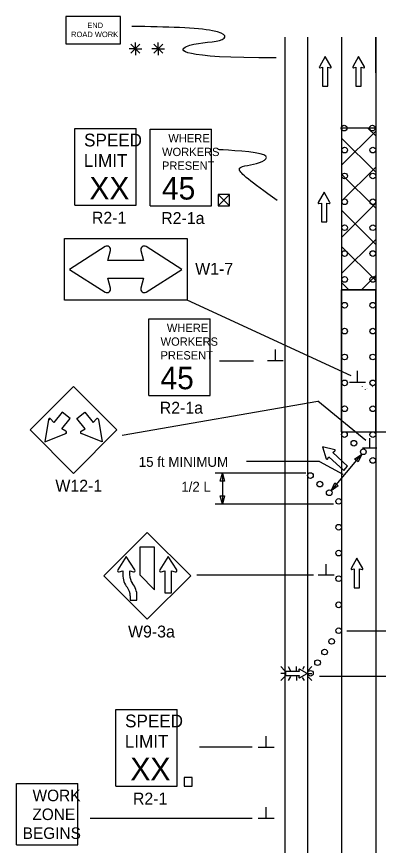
# Model space of a CAD drawing. Extents: x 16728 to 18482, y 5716 to 6919.
# Drawn here: x 16749 to 17004, y 6311 to 6894 of the extents above; entities that cross this region are included whole.
import ezdxf

# ---------------------------------------------------------------- set-up
doc = ezdxf.new("R2010")
doc.units = 0
for name, color, linetype in [('ALI_LEGAL_EX', 7, 'Continuous'), ('MT_SCRATCH_LEVEL_E', 7, 'Continuous'), ('PAVT_EDGE_EX', 7, 'Continuous'), ('TRAFFIC_SIGNS_PR', 7, 'Continuous'), ('TYPICAL_TEXT_DIMEN_PR', 7, 'Continuous')]:
    doc.layers.add(name, color=color, linetype=linetype)

msp = doc.modelspace()

# ---------------------------------------------------------------- linework, layer by layer
at = {"layer": 'ALI_LEGAL_EX'}
for p, q in [((16978.2, 6879.62), (16978.2, 6061.48)), ((17002.2, 6879.62), (17002.2, 6061.48))]:
    msp.add_line(p, q, dxfattribs=at)
for points in [[(16978.2, 6879.62), (16978.2, 6854.62)], [(17002.2, 6854.62), (17002.2, 6879.62)], [(17002.2, 6854.62), (17002.2, 6879.62)], [(16978.2, 6779.62), (16978.2, 6754.62)], [(17002.2, 6779.62), (17002.2, 6754.62)], [(16978.2, 6679.62), (16978.2, 6654.62)], [(17002.2, 6679.62), (17002.2, 6654.62)], [(17002.2, 6479.62), (17002.2, 6454.62)], [(16978.2, 6379.62), (16978.2, 6354.62)], [(17002.2, 6379.62), (17002.2, 6354.62)]]:
    msp.add_lwpolyline(points, dxfattribs=at)
at = {"layer": 'MT_SCRATCH_LEVEL_E'}
for p, q in [((16966.61, 6866.09), (16962.5, 6858.85)), ((16970.76, 6858.85), (16966.61, 6866.09)), ((16990.16, 6866.09), (16986.05, 6858.85)), ((16994.3, 6858.85), (16990.16, 6866.09)), ((16962.98, 6858.17), (16964.76, 6858.48)), ((16964.76, 6858.48), (16964.76, 6845.23)), ((16968.5, 6845.23), (16968.5, 6858.48)), ((16968.5, 6858.48), (16970.28, 6858.17)), ((16986.53, 6858.17), (16988.3, 6858.48)), ((16988.3, 6858.48), (16988.3, 6845.23)), ((16992.05, 6845.23), (16992.05, 6858.48)), ((16992.05, 6858.48), (16993.82, 6858.17)), ((16964.76, 6845.23), (16968.5, 6845.23)), ((16988.3, 6845.23), (16992.05, 6845.23)), ((16965.81, 6770.46), (16961.7, 6763.22)), ((16969.96, 6763.22), (16965.81, 6770.46)), ((16962.18, 6762.53), (16963.96, 6762.85)), ((16963.96, 6762.85), (16963.96, 6749.59)), ((16967.7, 6749.59), (16967.7, 6762.85)), ((16967.7, 6762.85), (16969.48, 6762.53)), ((16963.96, 6749.59), (16967.7, 6749.59)), ((16973.31, 6589.18), (16964.64, 6591.18)), ((16964.64, 6591.18), (16967.33, 6582.71)), ((16968.22, 6582.59), (16969.26, 6584.22)), ((16969.26, 6584.22), (16979.64, 6574.62)), ((16971.97, 6587.15), (16973.5, 6588.31)), ((16982.35, 6577.55), (16971.97, 6587.15)), ((16979.64, 6574.62), (16982.35, 6577.55)), ((16988.98, 6512.79), (16984.87, 6505.55)), ((16993.13, 6505.55), (16988.98, 6512.79)), ((16985.35, 6504.87), (16987.13, 6505.19)), ((16987.13, 6505.19), (16987.13, 6491.93)), ((16990.87, 6491.93), (16990.87, 6505.19)), ((16990.87, 6505.19), (16992.65, 6504.87)), ((16987.13, 6491.93), (16990.87, 6491.93))]:
    msp.add_line(p, q, dxfattribs=at)
for centre, radius, start, end in [((16962.91, 6858.63), 0.463, 150.42484, 279.96381), ((16970.35, 6858.63), 0.463, 260.03619, 29.77312), ((16986.45, 6858.63), 0.463, 150.42484, 279.96381), ((16993.89, 6858.63), 0.463, 260.03619, 29.77312), ((16962.1, 6762.99), 0.463, 150.42484, 279.96381), ((16969.55, 6762.99), 0.463, 260.03619, 29.77312), ((16973.19, 6588.7), 0.494, 307.28246, 77.01938), ((16967.8, 6582.87), 0.494, 197.6711, 327.21007), ((16985.28, 6505.33), 0.463, 150.42484, 279.96381), ((16992.72, 6505.33), 0.463, 260.03619, 29.77312)]:
    msp.add_arc(centre, radius, start, end, dxfattribs=at)
at = {"layer": 'PAVT_EDGE_EX'}
for p, q in [((16938.2, 6879.62), (16938.2, 6061.48)), ((16954.2, 6879.62), (16954.2, 6061.48)), ((16978.1, 6814.95), (16978.73, 6815.59)), ((17002.2, 6815.59), (16978.2, 6815.59)), ((16978.2, 6789.6), (17002.2, 6813.6)), ((17002.2, 6810.15), (16996.76, 6815.59)), ((17002.2, 6784.69), (16978.2, 6808.69)), ((16978.2, 6764.14), (17002.2, 6788.14)), ((17002.2, 6759.24), (16978.2, 6783.24)), ((16978.2, 6738.69), (17002.2, 6762.69)), ((17002.2, 6733.78), (16978.2, 6757.78)), ((16978.2, 6713.23), (17002.2, 6737.23)), ((17002.2, 6708.32), (16978.2, 6732.32)), ((16983.2, 6701.86), (16978.2, 6706.87)), ((16992.28, 6701.86), (17002.2, 6711.78)), ((16978.2, 6701.86), (17002.2, 6701.86)), ((16992.9, 6633.58), (16992.95, 6633.7)), ((16994.92, 6631.38), (16994.97, 6631.5)), ((16995.68, 6632.34), (16995.74, 6632.27)), ((16996.42, 6632.31), (16996.47, 6632.24)), ((16999.79, 6633.58), (16999.84, 6633.7))]:
    msp.add_line(p, q, dxfattribs=at)
msp.add_lwpolyline([(17002.24, 6701.84), (16977.87, 6701.84), (16977.87, 6601.86), (17002.24, 6601.86)], close=True, dxfattribs=at)
at = {"layer": 'TRAFFIC_SIGNS_PR'}
for p, q in [((16790.29, 6815.28), (16833.49, 6815.28)), ((16790.29, 6761.28), (16790.29, 6815.28)), ((16833.49, 6761.28), (16833.49, 6815.28)), ((16843.41, 6815), (16886.61, 6815)), ((16843.41, 6761), (16843.41, 6815)), ((16886.61, 6761), (16886.61, 6815)), ((16790.29, 6761.28), (16833.49, 6761.28)), ((16843.41, 6761), (16886.61, 6761)), ((16842.38, 6681.44), (16885.58, 6681.44)), ((16842.38, 6627.44), (16842.38, 6681.44)), ((16885.58, 6627.44), (16885.58, 6681.44)), ((16789.33, 6633.61), (16758.78, 6603.07)), ((16819.87, 6603.07), (16789.33, 6633.61)), ((16842.38, 6627.44), (16885.58, 6627.44)), ((16772.55, 6610.27), (16771.68, 6610.41)), ((16758.78, 6603.07), (16789.33, 6572.52)), ((16783.59, 6601.41), (16783.91, 6600.57)), ((16789.33, 6572.52), (16819.87, 6603.07)), ((16841.32, 6530.92), (16810.77, 6500.37)), ((16871.87, 6500.37), (16841.32, 6530.92)), ((16836.02, 6520.54), (16836.02, 6500.97)), ((16846.38, 6520.54), (16836.02, 6520.54)), ((16846.38, 6490.61), (16846.38, 6520.54)), ((16810.77, 6500.37), (16841.32, 6469.82)), ((16836.02, 6500.97), (16846.38, 6490.61)), ((16841.32, 6469.82), (16871.87, 6500.37)), ((16938.22, 6433.59), (16935.4, 6436.41)), ((16940.51, 6436.41), (16942.14, 6433.59)), ((16946.3, 6433.59), (16946.3, 6436.41)), ((16951.77, 6436.41), (16950.56, 6434.32)), ((16957.21, 6436.41), (16954.39, 6433.59)), ((16938.22, 6431.56), (16935.4, 6431.56)), ((16938.22, 6429.53), (16935.4, 6426.71)), ((16942.17, 6429.53), (16940.54, 6426.71)), ((16946.3, 6429.53), (16946.3, 6426.71)), ((16950.48, 6428.89), (16951.75, 6426.71)), ((16954.39, 6431.56), (16957.21, 6431.56)), ((16957.21, 6426.71), (16954.39, 6429.53)), ((16819.18, 6406.2), (16862.38, 6406.2)), ((16819.18, 6352.2), (16819.18, 6406.2)), ((16862.38, 6352.2), (16862.38, 6406.2)), ((16749.24, 6310.89), (16749.24, 6354.09)), ((16749.24, 6354.09), (16792.44, 6354.09)), ((16792.44, 6310.89), (16792.44, 6354.09)), ((16819.18, 6352.2), (16862.38, 6352.2)), ((16749.24, 6310.89), (16792.44, 6310.89))]:
    msp.add_line(p, q, dxfattribs=at)
for points in [[(16784.01, 6875), (16822.41, 6875), (16822.41, 6894.2), (16784.01, 6894.2)], [(16869.29, 6694.61), (16782.89, 6694.61), (16782.89, 6737.81), (16869.29, 6737.81)], [(16867.39, 6352.2), (16872.99, 6352.2), (16872.99, 6358.38), (16867.39, 6358.38)]]:
    msp.add_lwpolyline(points, close=True, dxfattribs=at)
for points in [[(16811.6, 6732.18), (16786.49, 6716.21), (16811.6, 6700.23)], [(16840.58, 6700.23), (16865.69, 6716.21), (16840.58, 6732.18)], [(16836.8, 6729.39), (16838.69, 6722.51), (16813.5, 6722.51), (16815.38, 6729.39)], [(16815.38, 6703.02), (16813.5, 6709.91), (16838.69, 6709.91), (16836.8, 6703.02)], [(16784.02, 6602.2), (16781.01, 6603.8), (16786.94, 6611.18), (16781.4, 6615.64), (16775.47, 6608.26), (16773.21, 6610.85)], [(16794.63, 6602.2), (16797.64, 6603.8), (16791.71, 6611.18), (16797.25, 6615.64), (16803.18, 6608.26), (16805.44, 6610.85)], [(16771.68, 6610.41), (16769.15, 6594.79), (16783.91, 6600.57)], [(16806.97, 6610.41), (16809.51, 6594.79), (16794.74, 6600.57)], [(16832.54, 6504.54), (16826.54, 6513.95), (16820.55, 6504.54)], [(16862.04, 6504.54), (16856.05, 6513.95), (16850.06, 6504.54)], [(16821.6, 6503.12), (16824.18, 6503.83), (16824.18, 6501.32)], [(16828.9, 6501.2), (16828.9, 6503.83), (16831.49, 6503.12)], [(16851.11, 6503.12), (16853.69, 6503.83), (16853.69, 6488.3), (16858.41, 6488.3), (16858.41, 6503.83), (16861, 6503.12)], [(16829.32, 6486.18), (16829.31, 6483.2), (16834.04, 6483.2), (16834.04, 6486.18)], [(16948.13, 6434.24), (16948.36, 6432.95), (16938.64, 6432.95), (16938.64, 6430.2), (16948.36, 6430.2), (16948.13, 6428.9)], [(16948.63, 6428.55), (16953.94, 6431.56), (16948.63, 6434.6)]]:
    msp.add_lwpolyline(points, dxfattribs=at)
for centre in [(16979.96, 6815.69), (16999.83, 6815.69), (16980.3, 6800.18), (17000.17, 6800.18), (16980.3, 6781.97), (17000.17, 6781.97), (16980.3, 6763.76), (17000.17, 6763.76), (16980.3, 6745.54), (17000.17, 6745.54), (16980.3, 6727.33), (17000.17, 6727.33), (16980.3, 6709.11), (17000.17, 6709.11), (16980.3, 6690.9), (17000.17, 6690.9), (16980.3, 6672.68), (17000.17, 6672.68), (16980.3, 6654.47), (17000.17, 6654.47), (16980.3, 6636.26), (17000.17, 6636.26), (16980.3, 6618.04), (17000.17, 6618.04), (16980.18, 6599.84), (17000.17, 6599.83), (16986.83, 6593.77), (16993.48, 6587.71), (17000.13, 6581.64), (16956.19, 6571.01), (16962.84, 6564.94), (16969.49, 6558.88), (16976.13, 6552.81), (16976.13, 6552.81), (16976.13, 6534.6), (16976.13, 6516.38), (16976.13, 6498.38), (16976.13, 6479.95), (16976.13, 6461.74), (16971.17, 6454.23), (16966.2, 6446.72), (16961.23, 6439.22), (16956.26, 6431.72)]:
    msp.add_circle(centre, 2, dxfattribs=at)
for centre, radius, start, end in [((16812.95, 6730.06), 2.52, 344.67308, 122.46963), ((16839.23, 6730.06), 2.52, 57.53038, 195.32692), ((16812.95, 6702.35), 2.52, 237.53038, 15.32692), ((16839.23, 6702.36), 2.52, 164.69282, 302.45235), ((16772.55, 6610.26), 0.885, 41.8659, 170.0393), ((16806.1, 6610.26), 0.885, 9.9607, 138.1341), ((16783.59, 6601.41), 0.9, 291.40774, 61.17916), ((16795.07, 6601.41), 0.9, 118.82084, 248.59226), ((16821.35, 6504.03), 0.945, 147.52044, 285.3986), ((16831.74, 6504.03), 0.947, 254.68281, 32.2708), ((16828.37, 6491.72), 11.81, 74.67996, 74.68078), ((16842.5, 6510.87), 11.81, 212.45689, 212.46649), ((16850.86, 6504.03), 0.946, 147.54971, 285.33159), ((16861.25, 6504.03), 0.943, 254.67777, 32.46648), ((16872.01, 6510.87), 11.81, 212.45689, 212.46649), ((16838.34, 6500.9), 14.17, 178.32933, 218.54273), ((16838.34, 6500.9), 9.45, 178.19356, 218.54646), ((16817.09, 6501.57), 11.81, 358.18937, 0.00483), ((16819.87, 6486.18), 9.45, 0, 38.54567), ((16819.87, 6486.18), 14.17, 0, 38.5422), ((16948.46, 6434.3), 0.341, 61.48329, 189.95933), ((16948.46, 6428.85), 0.341, 170.73078, 298.89165)]:
    msp.add_arc(centre, radius, start, end, dxfattribs=at)
at = {"layer": 'TYPICAL_TEXT_DIMEN_PR'}
for p, q in [((16832.96, 6871.52), (16832.96, 6875.98)), ((16849.02, 6871.52), (16849.02, 6875.98)), ((16832.96, 6871.52), (16828.43, 6871.52)), ((16829.77, 6874.71), (16836.15, 6868.34)), ((16836.15, 6874.71), (16829.77, 6868.34)), ((16832.96, 6871.52), (16836.15, 6871.52)), ((16832.96, 6871.52), (16837.44, 6871.52)), ((16832.96, 6871.52), (16832.96, 6867.02)), ((16849.02, 6871.52), (16844.49, 6871.52)), ((16852.21, 6874.71), (16845.83, 6868.34)), ((16845.84, 6874.71), (16852.21, 6868.34)), ((16849.02, 6871.52), (16852.21, 6871.52)), ((16849.02, 6871.52), (16853.5, 6871.52)), ((16849.02, 6871.52), (16849.02, 6867.02)), ((16891.27, 6761), (16899.27, 6769)), ((16891.28, 6769), (16899.27, 6761)), ((16984.9, 6641.27), (16869.29, 6694.61)), ((16931.51, 6651.86), (16931.51, 6659.65)), ((16892.13, 6651.86), (16916.22, 6651.86)), ((16937.13, 6651.86), (16925.88, 6651.86)), ((16989.46, 6636.84), (16989.46, 6644.63)), ((16983.84, 6636.84), (16995.09, 6636.84)), ((16823.63, 6599.33), (16961.39, 6623.3)), ((16995.16, 6595.74), (16961.39, 6623.3)), ((17002.25, 6601.86), (17091.2, 6601.86)), ((16998.03, 6590.27), (16998.03, 6597.28)), ((17003.09, 6590.27), (16992.96, 6590.27)), ((16970.86, 6560.33), (16992.31, 6586.09)), ((16987.35, 6582.59), (16992.31, 6586.09)), ((16992.31, 6586.09), (16989.76, 6580.58)), ((16962.71, 6580.86), (16911.24, 6580.86)), ((16962.71, 6580.86), (16979.12, 6572.02)), ((16988.56, 6581.58), (16987.35, 6582.59)), ((16989.76, 6580.58), (16988.56, 6581.58)), ((16952.92, 6572.78), (16889.2, 6572.78)), ((16892.63, 6566.92), (16894.2, 6572.78)), ((16894.2, 6572.78), (16894.2, 6550.81)), ((16894.2, 6572.78), (16895.77, 6566.92)), ((16894.2, 6566.92), (16892.63, 6566.92)), ((16895.77, 6566.92), (16894.2, 6566.92)), ((16970.86, 6560.33), (16973.41, 6565.84)), ((16975.82, 6563.83), (16970.86, 6560.33)), ((16973.41, 6565.84), (16974.61, 6564.83)), ((16974.61, 6564.83), (16975.82, 6563.83)), ((16894.2, 6550.81), (16892.63, 6556.67)), ((16892.63, 6556.67), (16894.2, 6556.67)), ((16894.2, 6556.67), (16895.77, 6556.67)), ((16895.77, 6556.67), (16894.2, 6550.81)), ((16972.37, 6550.81), (16889.2, 6550.81)), ((16967.24, 6500.81), (16967.24, 6508.59)), ((16958.41, 6500.81), (16876.2, 6500.81)), ((16972.86, 6500.81), (16961.61, 6500.81)), ((16981.95, 6461.74), (17126.01, 6461.74)), ((16962.6, 6429.63), (17091.2, 6429.63)), ((16925.07, 6379.63), (16925.07, 6387.42)), ((16915.2, 6379.63), (16878.09, 6379.63)), ((16919.45, 6379.63), (16930.7, 6379.63)), ((16925.07, 6329.63), (16925.07, 6337.42)), ((16801.11, 6329.63), (16915.2, 6329.63)), ((16919.45, 6329.63), (16930.7, 6329.63))]:
    msp.add_line(p, q, dxfattribs=at)
msp.add_lwpolyline([(16891.28, 6769), (16891.27, 6761), (16899.27, 6761), (16899.27, 6769)], close=True, dxfattribs=at)
for points in [[(16932.08, 6865.07), (16863.08, 6865.07), (16863.08, 6875.83), (16897.99, 6875.83), (16897.99, 6885.49), (16855.13, 6887.01), (16830.34, 6887.27)], [(16932.82, 6764.58), (16913.88, 6778.39), (16899.1, 6789.14), (16919.17, 6789.14), (16934.02, 6798.8), (16891.16, 6800.32), (16891.39, 6800.58)]]:
    msp.add_open_spline(points, degree=3, dxfattribs=at)

# ---------------------------------------------------------------- texts
at = {"layer": 'TRAFFIC_SIGNS_PR'}
for s, height, p in [('END', 3.831, (16799.01, 6886.13)), ('ROAD WORK', 3.831, (16787.62, 6879.75)), ('SPEED', 9, (16796.77, 6802.75)), ('WHERE', 5.85, (16856.13, 6805.65)), ('WORKERS', 5.85, (16851.71, 6795.97)), ('LIMIT', 9, (16796.59, 6788.35)), ('PRESENT', 5.85, (16851.64, 6786.3)), ('XX', 15.785, (16800.54, 6765.51)), ('45', 15.785, (16851.63, 6765.34)), ('R2-1', 8.37, (16802.3, 6748.41)), ('R2-1a', 8.37, (16851.12, 6748.13)), ('W1-7', 8.37, (16875.04, 6712.39)), ('WHERE', 5.85, (16855.1, 6672.08)), ('WORKERS', 5.85, (16850.69, 6662.41)), ('PRESENT', 5.85, (16850.61, 6652.73)), ('45', 15.785, (16850.6, 6631.77)), ('R2-1a', 8.37, (16850.09, 6614.57)), ('W12-1', 8.37, (16776.59, 6559.65)), ('W9-3a', 8.37, (16827.75, 6456.95)), ('SPEED', 9, (16825.66, 6393.67)), ('LIMIT', 9, (16825.48, 6379.27)), ('XX', 15.785, (16829.43, 6356.43)), ('WORK', 8.119, (16760.49, 6341.67)), ('R2-1', 8.37, (16831.19, 6339.33)), ('ZONE', 8.119, (16760.35, 6328.39)), ('BEGINS', 8.119, (16753.52, 6315.1))]:
    msp.add_text(s, height=height, dxfattribs=at).set_placement(p)
at = {"layer": 'TYPICAL_TEXT_DIMEN_PR'}
for s, p in [('15 ft MINIMUM', (16835.32, 6577.13)), ('1/2 L', (16865.27, 6559.62))]:
    msp.add_text(s, height=7, dxfattribs=at).set_placement(p)

doc.saveas('drawing.dxf')
